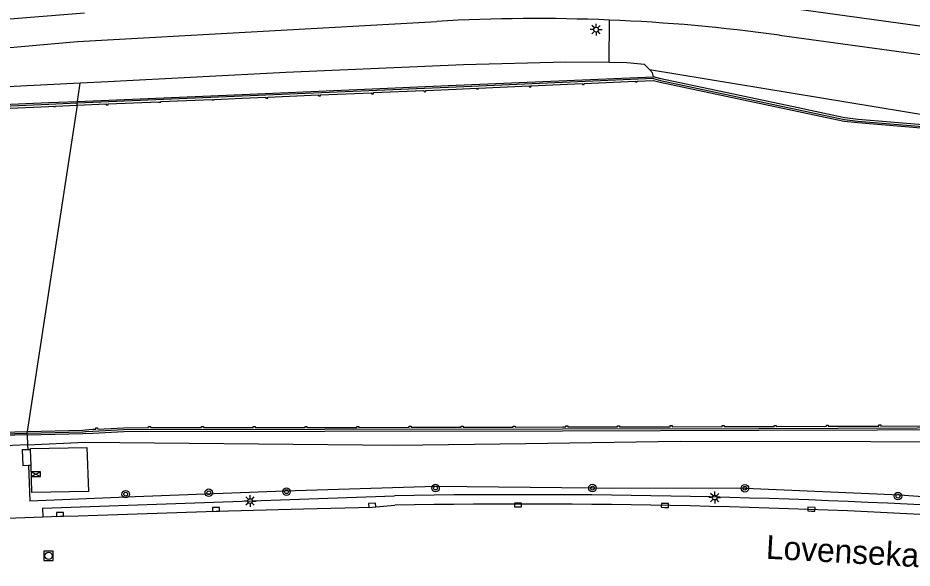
# Model space of a CAD drawing. Extents: x 132999 to 136000, y 398499 to 400501.
# Drawn here: x 134050.2 to 134144.6, y 398906.5 to 398964.6 of the extents above; entities that cross this region are included whole.
import ezdxf

# ---------------------------------------------------------------- set-up
doc = ezdxf.new("R2010")
doc.units = 0
for name, color, linetype in [('gg-afsc-muur', 7, 'Continuous'), ('gg-anno-openbare ruimte label', 7, 'Continuous'), ('gg-knt-BGT kruinlijn', 7, 'Continuous'), ('gg-knt-verharding', 7, 'Continuous'), ('gg-kwrk-betonelement', 7, 'Continuous'), ('gt-grn-groengrens', 7, 'Continuous'), ('gt-symb-boom', 7, 'Continuous'), ('gt-symb-kolk', 7, 'Continuous'), ('gt-symb-lichtmast', 7, 'Continuous'), ('gt-symb-rioolkast', 7, 'Continuous'), ('gt-symb-rioolschacht', 7, 'Continuous'), ('gx-grn-maaiveld', 7, 'Continuous')]:
    doc.layers.add(name, color=color, linetype=linetype)

# ---------------------------------------------------------------- blocks, each defined once
blk = doc.blocks.new('gt0-RKAST')
at = {"layer": 'gt-symb-rioolkast'}
for p, q in [((-0.501, -0.249), (0.501, 0.249)), ((-0.501, 0.249), (0.501, -0.249))]:
    blk.add_line(p, q, dxfattribs=at)
blk.add_lwpolyline([(0.501, 0.249), (-0.501, 0.249), (-0.501, -0.249), (0.501, -0.249)], close=True, dxfattribs=at)
blk = doc.blocks.new('gt0-RS')
at = {"layer": 'gt-symb-rioolschacht'}
blk.add_lwpolyline([(-0.5, -0.5), (0.5, -0.5), (0.5, 0.5), (-0.5, 0.5)], close=True, dxfattribs=at)
blk.add_circle((0, 0), 0.375, dxfattribs=at)
blk = doc.blocks.new('gt0-KOLK')
at = {"layer": 'gt-symb-kolk'}
blk.add_lwpolyline([(0, 0), (0.375, 0), (0.375, 0.4), (-0.375, 0.4), (-0.375, 0), (0, 0)], dxfattribs=at)
blk = doc.blocks.new('gt0-BOOM')
at = {"layer": 'gt-symb-boom'}
for radius in [0.4, 0.2]:
    blk.add_circle((0, 0), radius, dxfattribs=at)
blk = doc.blocks.new('gt0-LMAST')
at = {"layer": 'gt-symb-lichtmast'}
for p, q in [((-0.182, 0.173), (-0.447, 0.438)), ((-0.005, 0.246), (-0.005, 0.621)), ((0.172, 0.173), (0.437, 0.438)), ((-0.255, -0.004), (-0.63, -0.004)), ((-0.182, -0.181), (-0.447, -0.446)), ((-0.005, -0.254), (-0.005, -0.629)), ((0.437, -0.446), (0.172, -0.181)), ((0.245, -0.004), (0.62, -0.004))]:
    blk.add_line(p, q, dxfattribs=at)
blk.add_circle((-0.005, -0.004), 0.25, dxfattribs=at)

msp = doc.modelspace()

# ---------------------------------------------------------------- linework, layer by layer
at = {"layer": 'gg-afsc-muur'}
for points in [[(134117.336, 398958.144), (134096.488, 398957.237), (134073.895, 398956.273), (134056.494, 398955.542)], [(134117.336, 398958.144), (134118.072, 398957.949), (134136.162, 398954.119), (134137.49, 398953.812), (134138.921, 398953.666), (134155.994, 398952.244), (134156.833, 398952.164), (134162.774, 398951.499), (134172.613, 398950.4), (134186.48, 398948.606), (134200.474, 398946.526), (134214.269, 398944.182), (134228.118, 398941.58), (134241.93, 398938.614), (134255.707, 398935.488), (134269.39, 398932.046), (134282.842, 398928.317), (134295.149, 398924.738), (134308.352, 398920.539), (134321.777, 398916.074), (134336.3, 398910.948)], [(134056.494, 398955.542), (134053.481, 398955.415), (134030.174, 398954.398)], [(134057.348, 398920.868), (134058.126, 398920.91), (134061.385, 398921.083), (134082.614, 398921.11), (134107.721, 398921.164), (134128.454, 398921.208), (134153.511, 398921.29), (134176.516, 398921.337)], [(134033.463, 398920.12), (134044.585, 398920.526), (134051.204, 398920.704)], [(134051.204, 398920.704), (134057.071, 398920.861), (134057.348, 398920.868)]]:
    msp.add_lwpolyline(points, dxfattribs=at)
at = {"layer": 'gg-knt-BGT kruinlijn'}
for p, q in [((134097.275, 398959.593), (134078.519, 398958.78)), ((134108.086, 398959.882), (134097.275, 398959.593)), ((134112.642, 398959.833), (134108.086, 398959.882)), ((134114.526, 398959.813), (134112.642, 398959.833)), ((134116.397, 398959.651), (134114.526, 398959.813)), ((134116.918, 398959.093), (134116.397, 398959.651)), ((134116.918, 398959.093), (134147.341, 398954.08)), ((134116.918, 398959.093), (134117.233, 398958.755)), ((134078.519, 398958.78), (134059.712, 398957.793)), ((134117.327, 398958.344), (134117.233, 398958.755)), ((134056.812, 398957.648), (134049.129, 398957.264)), ((134059.712, 398957.793), (134056.812, 398957.648)), ((134051.234, 398919.472), (134044.707, 398919.181)), ((134051.234, 398919.472), (134057.335, 398919.743)), ((134057.335, 398919.743), (134090.255, 398919.452)), ((134090.255, 398919.452), (134103.838, 398919.607)), ((134103.838, 398919.607), (134120.129, 398919.85)), ((134120.129, 398919.85), (134140.263, 398919.813)), ((134140.263, 398919.813), (134156.28, 398919.744))]:
    msp.add_line(p, q, dxfattribs=at)
at = {"layer": 'gg-knt-verharding'}
for p, q in [((134032.297, 398963.092), (134057.235, 398965.072)), ((134051.548, 398918.957), (134051.256, 398918.947)), ((134051.325, 398917.326), (134051.606, 398917.336)), ((134044.815, 398911.564), (134052.866, 398911.865))]:
    msp.add_line(p, q, dxfattribs=at)
for points in [[(134115.662, 398967.283), (134124.221, 398966.67), (134149.051, 398963.23), (134156.832, 398962.252)], [(134033.101, 398960), (134056.521, 398962.07), (134094.438, 398964.19)], [(134130.63, 398962.734), (134148.891, 398960.23), (134182.341, 398956.021)], [(134051.256, 398918.947), (134050.665, 398918.927), (134050.741, 398917.305), (134051.325, 398917.326)], [(134056.584, 398911.991), (134071.144, 398912.456), (134080.367, 398912.715), (134087.63, 398912.897), (134090.01, 398913.1)], [(134052.866, 398911.865), (134054.668, 398911.932), (134056.584, 398911.991)]]:
    msp.add_lwpolyline(points, dxfattribs=at)
for centre, radius, start, end in [((134104.981, 398775.532), 188.953, 87.66164, 93.19847), ((134105.001, 398775.925), 188.558, 82.18826, 87.66308), ((134103.453, 398095.857), 817.353, 86.277396, 90.942353)]:
    msp.add_arc(centre, radius, start, end, dxfattribs=at)
at = {"layer": 'gg-kwrk-betonelement'}
msp.add_line((134051.606, 398917.336), (134051.548, 398918.957), dxfattribs=at)
msp.add_lwpolyline([(134051.548, 398918.957), (134051.543, 398919.094), (134057.515, 398919.19), (134057.681, 398914.528), (134051.709, 398914.433), (134051.606, 398917.336)], dxfattribs=at)
at = {"layer": 'gt-grn-groengrens'}
for p, q in [((134112.642, 398959.833), (134112.69, 398964.327)), ((134052.833, 398912.768), (134089.994, 398914.1)), ((134052.833, 398912.768), (134052.866, 398911.865))]:
    msp.add_line(p, q, dxfattribs=at)
msp.add_arc((134103.434, 398095.267), 818.943, 86.278058, 90.94033, dxfattribs=at)
at = {"layer": 'gx-grn-maaiveld'}
for p, q in [((134056.524, 398955.743), (134056.812, 398957.648)), ((134056.464, 398955.34), (134051.199, 398920.879)), ((134056.464, 398955.34), (134056.524, 398955.743)), ((134051.208, 398920.529), (134051.199, 398920.879)), ((134051.208, 398920.529), (134051.234, 398919.472)), ((134051.234, 398919.472), (134051.256, 398918.947)), ((134051.325, 398917.326), (134051.487, 398913.535))]:
    msp.add_line(p, q, dxfattribs=at)
for points in [[(134056.524, 398955.743), (134073.886, 398956.473), (134096.479, 398957.437), (134117.327, 398958.344)], [(134132.615, 398955.049), (134118.109, 398958.12), (134117.328, 398958.327), (134117.327, 398958.344)], [(134056.464, 398955.34), (134059.541, 398955.47), (134059.545, 398955.381), (134059.745, 398955.39), (134059.741, 398955.478), (134065.109, 398955.704), (134065.111, 398955.664), (134065.311, 398955.673), (134065.309, 398955.712), (134070.732, 398955.94), (134070.734, 398955.902), (134070.934, 398955.911), (134070.932, 398955.949), (134073.903, 398956.073), (134076.399, 398956.18), (134076.403, 398956.086), (134076.603, 398956.095), (134076.598, 398956.188), (134081.962, 398956.417), (134081.967, 398956.312), (134082.167, 398956.321), (134082.162, 398956.426), (134087.551, 398956.656), (134087.557, 398956.533), (134087.757, 398956.542), (134087.751, 398956.664), (134093.093, 398956.892), (134093.099, 398956.758), (134093.298, 398956.767), (134093.293, 398956.901), (134096.496, 398957.037), (134098.64, 398957.131), (134098.644, 398957.048), (134098.844, 398957.057), (134098.84, 398957.139), (134104.192, 398957.372), (134104.197, 398957.262), (134104.397, 398957.271), (134104.392, 398957.381), (134109.815, 398957.617), (134109.819, 398957.522), (134110.019, 398957.531), (134110.014, 398957.626), (134115.421, 398957.861), (134115.424, 398957.793), (134115.623, 398957.802), (134115.621, 398957.869), (134117.344, 398957.944), (134117.344, 398957.961), (134118.036, 398957.778), (134136.124, 398953.948), (134137.461, 398953.639), (134138.905, 398953.492), (134155.978, 398952.07)], [(134030.12, 398954.596), (134053.472, 398955.615), (134056.524, 398955.743)], [(134030.182, 398954.198), (134031.53, 398954.257), (134031.535, 398954.143), (134031.735, 398954.152), (134031.73, 398954.266), (134037.173, 398954.503), (134037.176, 398954.435), (134037.375, 398954.444), (134037.373, 398954.512), (134042.793, 398954.749), (134042.795, 398954.699), (134042.995, 398954.708), (134042.992, 398954.757), (134048.392, 398954.993), (134048.394, 398954.955), (134048.594, 398954.964), (134048.592, 398955.002), (134053.489, 398955.215), (134053.974, 398955.236), (134053.977, 398955.185), (134054.177, 398955.194), (134054.174, 398955.244), (134056.464, 398955.34)], [(134336.359, 398911.112), (134321.833, 398916.239), (134308.406, 398920.706), (134295.2, 398924.906), (134282.89, 398928.486), (134269.434, 398932.215), (134255.747, 398935.658), (134241.967, 398938.785), (134228.152, 398941.751), (134214.3, 398944.355), (134200.501, 398946.699), (134186.504, 398948.78), (134172.634, 398950.574), (134162.794, 398951.673), (134156.851, 398952.338), (134156.009, 398952.419), (134138.937, 398953.841), (134137.518, 398953.985), (134136.2, 398954.29), (134132.615, 398955.049)], [(134051.199, 398920.879), (134057.066, 398921.036), (134057.339, 398921.043), (134057.338, 398921.068), (134058.116, 398921.109), (134058.45, 398921.127), (134058.443, 398921.269), (134058.642, 398921.279), (134058.649, 398921.138), (134061.379, 398921.283), (134064.005, 398921.286), (134064.005, 398921.413), (134064.205, 398921.413), (134064.205, 398921.287), (134069.602, 398921.293), (134069.602, 398921.419), (134069.802, 398921.419), (134069.802, 398921.294), (134075.066, 398921.3), (134075.066, 398921.405), (134075.266, 398921.405), (134075.266, 398921.301), (134080.541, 398921.307), (134080.541, 398921.419), (134080.741, 398921.419), (134080.741, 398921.308), (134082.613, 398921.31), (134086.006, 398921.317), (134086.006, 398921.419), (134086.206, 398921.419), (134086.206, 398921.318), (134091.534, 398921.329), (134091.534, 398921.435), (134091.734, 398921.435), (134091.734, 398921.33), (134097.021, 398921.341), (134097.021, 398921.432), (134097.221, 398921.432), (134097.221, 398921.341), (134102.519, 398921.353), (134102.519, 398921.442), (134102.719, 398921.442), (134102.719, 398921.353), (134107.72, 398921.364), (134108.068, 398921.365), (134108.068, 398921.474), (134108.268, 398921.474), (134108.268, 398921.365), (134113.541, 398921.376), (134113.541, 398921.484), (134113.741, 398921.484), (134113.741, 398921.377), (134119.089, 398921.388), (134119.089, 398921.499), (134119.289, 398921.499), (134119.289, 398921.389), (134124.58, 398921.4), (134124.58, 398921.524), (134124.78, 398921.524), (134124.78, 398921.4), (134128.454, 398921.408), (134130.078, 398921.413), (134130.078, 398921.522), (134130.278, 398921.522), (134130.278, 398921.414), (134135.582, 398921.431), (134135.582, 398921.561), (134135.782, 398921.561), (134135.782, 398921.432), (134141.118, 398921.449), (134141.118, 398921.599), (134141.318, 398921.599), (134141.318, 398921.449), (134146.661, 398921.468)], [(134033.407, 398920.293), (134044.579, 398920.701), (134051.199, 398920.879)], [(134051.208, 398920.529), (134044.591, 398920.351), (134033.42, 398919.943)], [(134051.208, 398920.529), (134057.077, 398920.686), (134057.358, 398920.694), (134057.359, 398920.669), (134058.137, 398920.71), (134061.39, 398920.883), (134082.614, 398920.91), (134107.721, 398920.964), (134128.455, 398921.008), (134153.512, 398921.09), (134176.516, 398921.137)], [(134343.541, 398868.113), (134328.547, 398874.11), (134313.014, 398879.69), (134305.66, 398881.774), (134302.764, 398882.848), (134299.271, 398884.774), (134283.736, 398889.606), (134268.797, 398894.223), (134245.272, 398900.49), (134230.482, 398904.215), (134214.843, 398907.143), (134206.05, 398908.511), (134190.925, 398910.186), (134175.228, 398911.682), (134159.208, 398912.988), (134143.336, 398914.154), (134127.057, 398914.873), (134110.94, 398914.88), (134094.347, 398915.09), (134078.374, 398914.565), (134062.619, 398913.967), (134051.487, 398913.535)]]:
    msp.add_lwpolyline(points, dxfattribs=at)

# ---------------------------------------------------------------- block references
at = {"layer": 'gt-symb-boom'}
for p in [(134061.604, 398914.263), (134070.379, 398914.412), (134078.58, 398914.524), (134094.315, 398914.912), (134110.886, 398914.902), (134126.978, 398914.889), (134143.139, 398914.053)]:
    msp.add_blockref('gt0-BOOM', p, dxfattribs=at)
at = {"layer": 'gt-symb-kolk'}
for p, rotation in [((134071.144, 398912.456), 1.6061537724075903), ((134087.63, 398912.897), 4.872213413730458), ((134103.033, 398912.924), 0.2864765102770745), ((134118.527, 398912.87), -0.8593722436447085), ((134133.995, 398912.472), -2.063819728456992), ((134054.668, 398911.932), 1.775544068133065)]:
    msp.add_blockref('gt0-KOLK', p, dxfattribs=dict(at, rotation=rotation))
at = {"layer": 'gt-symb-lichtmast'}
for p in [(134111.279, 398963.319), (134074.746, 398913.538), (134123.795, 398913.912)]:
    msp.add_blockref('gt0-LMAST', p, dxfattribs=at)
at = {"layer": 'gt-symb-rioolkast'}
msp.add_blockref('gt0-RKAST', (134052.12, 398916.389), dxfattribs=at)
at = {"layer": 'gt-symb-rioolschacht'}
msp.add_blockref('gt0-RS', (134053.455, 398907.75), dxfattribs=at)

# ---------------------------------------------------------------- texts
at = {"layer": 'gg-anno-openbare ruimte label'}
msp.add_text('Lovensekanaaldijk', height=2.5, rotation=356.8, dxfattribs=at).set_placement((134129.159, 398907.455))

doc.saveas('drawing.dxf')
